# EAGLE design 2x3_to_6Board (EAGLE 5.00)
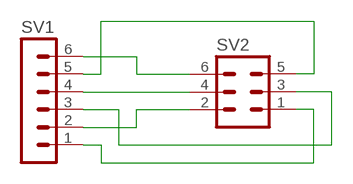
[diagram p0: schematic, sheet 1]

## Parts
SV1  MA06-1  [MA06-1]
SV2  MA03-2  [MA03-2]

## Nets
N$1: SV1.6 SV2.6
N$2: SV1.4 SV2.4
N$3: SV1.2 SV2.2
N$4: SV1.5 SV2.5
N$5: SV1.3 SV2.3
N$6: SV1.1 SV2.1

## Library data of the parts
SV1 = con-lstb:MA06-1: PIN HEADER
SV2 = con-lstb:MA03-2: PIN HEADER

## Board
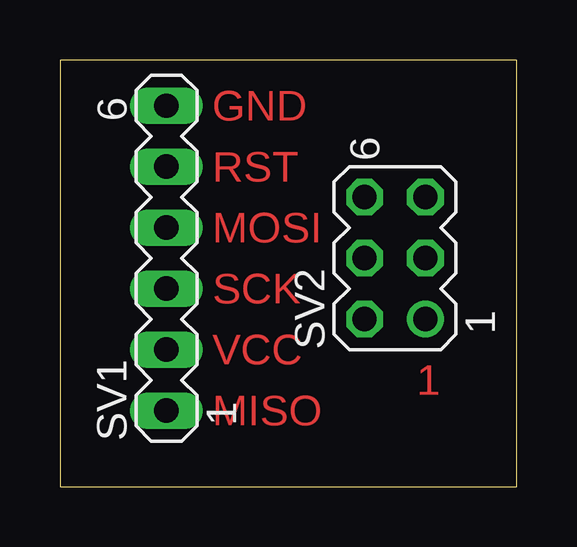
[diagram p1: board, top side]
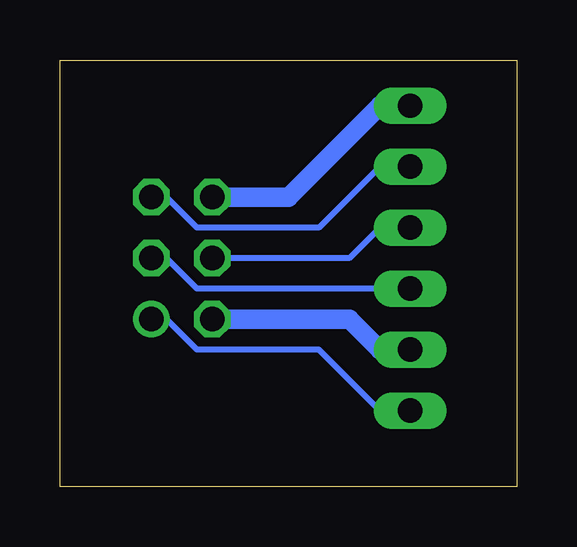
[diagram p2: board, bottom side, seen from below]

Size 19.05 x 17.78 mm. Coordinates in mm from the lower left corner, seen from the top.
Outline: 0,0 19.05,0 19.05,17.78 0,17.78 0,0
Copper layers (1*16): Top 0.035mm / dielectric 1.5mm / Bottom 0.035mm
Design rules "default": minimum track width 10mil, minimum drill 24mil, track to track 8mil, track to pad 8mil, pad to pad 8mil, via to via 8mil, smd to smd 8mil, copper to edge 40mil, drill to drill 8mil, minimum pad ring 10mil, minimum via ring 8mil, stop-mask expansion 4mil, vias tented up to drill 0mil, thermal gap 10mil

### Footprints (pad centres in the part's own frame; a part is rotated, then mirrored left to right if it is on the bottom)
MA06-1 = drill 1.016 long: 1 -6.35,0; 2 -3.81,0; 3 -1.27,0; 4 1.27,0; 5 3.81,0; 6 6.35,0
MA03-2 = drill 1.016 round: 1 -2.54,-1.27 | drill 1.016 octagon: 2 -2.54,1.27; 3 0,-1.27; 4 0,1.27; 5 2.54,-1.27; 6 2.54,1.27

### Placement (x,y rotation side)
SV1  4.45,9.53 90 top
SV2  13.97,9.53 90 top

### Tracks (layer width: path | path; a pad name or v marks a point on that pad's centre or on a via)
N$1
  Bottom 0.813: SV1.6 5.71,15.88 9.53,12.06 SV2.6
N$2
  Bottom 0.254: SV1.4 5.71,10.79 6.98,9.53 SV2.4
N$3
  Bottom 0.813: SV1.2 5.71,5.71 6.98,6.98 SV2.2
N$4
  Bottom 0.254: SV1.5 5.71,13.33 8.26,10.79 13.33,10.79 14.61,12.06 SV2.5
N$5
  Bottom 0.254: SV1.3 13.33,8.26 14.61,9.53 SV2.3
N$6
  Bottom 0.254: SV1.1 5.71,3.17 8.26,5.71 13.33,5.71 14.61,6.98 SV2.1

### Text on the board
Top: GND | RST | MOSI | SCK | VCC | 1 | MISO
